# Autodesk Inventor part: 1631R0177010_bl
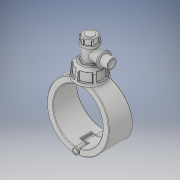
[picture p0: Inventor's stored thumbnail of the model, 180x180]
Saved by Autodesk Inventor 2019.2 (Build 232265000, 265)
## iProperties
Created: 2022-02
Part Number: 1631R0177010_bl
Material: Generic
Description: Plassadle Tapper Male 177x1''
Document SubType Name: Modeling
Designer: comp2
Density: 1 g/cm^3
Appearance: Default
Author: comp2
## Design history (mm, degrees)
derived "1631R.ipt"
feature "Solid1::1631R.ipt" dims "ScaleForDerivedMember" = 10
feature "Solid2::1631R.ipt" dims "ScaleForDerivedMember" = 10
feature "Solid3::1631R.ipt" dims "ScaleForDerivedMember" = 10
feature "Solid4::1631R.ipt" dims "ScaleForDerivedMember" = 10
tag "TaggingFeature1"
body "Solid1"
body "Solid2"
body "Solid3"
body "Solid4"
other parameters: "d0" = 177 [user parameter], "d3" = 88.5 [user parameter], "d7" = 209 [user parameter], "d8" = 85 deg [user parameter], "d9" = 45 deg [user parameter], "d10" = 102 [user parameter], "d11" = 52 [user parameter], "d12" = 36.4 [user parameter], "d13" = 42.84 [user parameter], "d14" = 57.936 [user parameter], "d15" = 2.6 [user parameter], "d16" = 2 [user parameter], "d17" = 2 [user parameter], "d18" = 31.2 [user parameter], "d19" = 7.8 [user parameter], "d20" = 1 [user parameter], "d21" = 30.6 [user parameter], "d22" = 1 [user parameter], "d23" = 15.6 [user parameter], "d24" = 78 [user parameter], "d27" = 144 [user parameter], "d29" = 49.8735 [user parameter], "d31" = 33.249 [user parameter], "d32" = 31.2 [user parameter], "d33" = 26.52 [user parameter], "d41" = 5 [user parameter], "d42" = 4.3 [user parameter], "d46" = 56.1 [user parameter], "d47" = 36.5739 [user parameter], "d48" = 52 [user parameter], "d49" = 4.4 [user parameter], "d51" = 0 [user parameter], "d52" = 30.1 [user parameter], "d53" = 121 [user parameter], "d54" = 38.5 [user parameter], "d55" = 0 [user parameter], "d56" = 22 [user parameter], "d57" = 22 [user parameter], "d59" = 0 [user parameter], "d61" = 0 [user parameter], "d62" = 38.5 [user parameter], "d63" = 0 [user parameter], "d65" = 0 [user parameter], "d67" = 0 [user parameter], "d69" = 0 [user parameter], "d70" = 1 [user parameter], "d71" = 105.6 [user parameter], "d72" = 0 [user parameter], "d73" = 2 [user parameter], "d77" = 24.93675 [user parameter], "d78" = 86.7 [user parameter], "d79" = 5.1 [user parameter], "d80" = 60 deg [user parameter], "d81" = 5.1 [user parameter], "d84" = 0 [user parameter], "d85" = 1 [user parameter], "d87" = 360 deg [user parameter], "d90" = 0 [user parameter], "d91" = 1 [user parameter], "d93" = 60 deg [user parameter], "d94" = 3.06 [user parameter], "d95" = 3.06 [user parameter], "d97" = 0 [user parameter], "d98" = 0.5 [user parameter], "d100" = 360 deg [user parameter], "d102" = 2 [user parameter], "d117" = 0.5 [user parameter], "d118" = 31.2 [user parameter], "d119" = 100 deg [user parameter], "d121" = 0 [user parameter], "d" = 177 [user parameter], "d1" = 25 [user parameter], "E_" = 54 [user parameter], "E1" = 102 [user parameter], "H2" = 144 [user parameter], "H3" = 78 [user parameter], "H_costum" = 52 [user parameter], "R" = 33.249 [user parameter]
